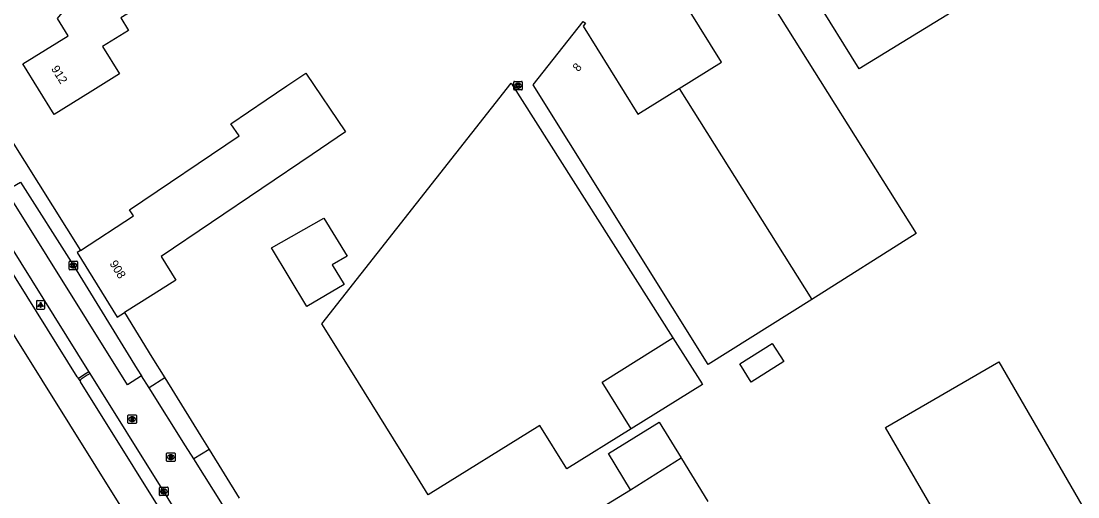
# Model space of a CAD drawing. Extents: x 158461 to 159795, y 387220 to 388672.
# Drawn here: x 158755 to 158879.5, y 387329 to 387385 of the extents above; entities that cross this region are included whole.
import ezdxf

# ---------------------------------------------------------------- set-up
doc = ezdxf.new("R2010")
doc.units = 0
for name, color, linetype in [('IMGEO_Brandkraan', 7, 'Continuous'), ('IMGEO_Haag', 7, 'Continuous'), ('IMGEO_Kolk', 7, 'Continuous'), ('IMGEO_Lichtpunt', 7, 'Continuous'), ('IMGEO_Pand', 7, 'Continuous'), ('IMGEO_Pand_nummerreeks', 7, 'Continuous'), ('IMGEO_Rijbaan_lokaal_open', 7, 'Continuous'), ('IMGEO_Rijbaan_regionaal_gesloten', 7, 'Continuous'), ('IMGEO_Rioolput', 7, 'Continuous'), ('IMGEO_Voetpad_open', 7, 'Continuous')]:
    doc.layers.add(name, color=color, linetype=linetype)

msp = doc.modelspace()

# ---------------------------------------------------------------- linework, layer by layer
at = {"layer": 'IMGEO_Brandkraan'}
for p, q in [((158772.16, 387333.25), (158772.16, 387334.1)), ((158772.24, 387334.18), (158773.09, 387334.18)), ((158772.65, 387333.96), (158772.68, 387333.96)), ((158772.67, 387333.4), (158772.65, 387333.4)), ((158773.16, 387334.1), (158773.16, 387333.25)), ((158773.09, 387333.18), (158772.24, 387333.18))]:
    msp.add_line(p, q, dxfattribs=at)
for points in [[(158772.16, 387333.25), (158772.16, 387334.1)], [(158772.24, 387334.18), (158773.09, 387334.18)], [(158772.51, 387333.88), (158772.51, 387333.48), (158772.72, 387333.48)], [(158772.74, 387333.88), (158772.51, 387333.88)], [(158772.69, 387333.8), (158772.63, 387333.8), (158772.63, 387333.72)], [(158772.63, 387333.72), (158772.69, 387333.72)], [(158772.7, 387333.64), (158772.63, 387333.64), (158772.63, 387333.56)], [(158772.63, 387333.56), (158772.7, 387333.56)], [(158773.16, 387334.1), (158773.16, 387333.25)], [(158773.09, 387333.18), (158772.24, 387333.18)]]:
    msp.add_lwpolyline(points, dxfattribs=at)
for centre, radius, start, end in [((158772.24, 387334.1), 0.0765, 91.552, 178.448), ((158772.24, 387334.1), 0.0765, 91.552, 178.448), ((158772.24, 387333.25), 0.0765, 181.552, 268.448), ((158772.24, 387333.25), 0.0765, 181.552, 268.448), ((158772.69, 387333.76), 0.0379, 267.8285, 90.9355), ((158772.7, 387333.6), 0.0404, 269.8759, 90.5077), ((158772.73, 387333.73), 0.251, 268.6676, 293.5347), ((158772.75, 387333.73), 0.145, 59.4692, 91.5367), ((158772.77, 387333.78), 0.0922, 285.5137, 58.1501), ((158772.77, 387333.59), 0.105, 301.3115, 78.989), ((158773.09, 387334.1), 0.0765, 1.552, 88.448), ((158773.09, 387334.1), 0.0765, 1.552, 88.448), ((158773.09, 387333.25), 0.0765, 271.552, 358.448), ((158773.09, 387333.25), 0.0765, 271.552, 358.448)]:
    msp.add_arc(centre, radius, start, end, dxfattribs=at)
for centre, major_axis, ratio, start_param, end_param in [((158772.65, 387333.68), (-0.387, 0.002), 0.722429, 4.712389, 7.853982), ((158772.67, 387333.68), (-0.39, 0.002), 0.717154, 1.570796, 4.712389)]:
    msp.add_ellipse(centre, major_axis=major_axis, ratio=ratio, start_param=start_param, end_param=end_param, dxfattribs=at)
at = {"layer": 'IMGEO_Haag'}
for points in [[(158761.92, 387343.05), (158762.69, 387343.55), (158763.01, 387343.76)], [(158763.16, 387343.53), (158762.83, 387343.32), (158762.11, 387342.85)]]:
    msp.add_lwpolyline(points, dxfattribs=at)
for centre, radius, start, end in [((158761.82, 387343.19), 0.176, 248.8695, 305.5504), ((158762.26, 387342.65), 0.255, 126.1975, 177.1656)]:
    msp.add_arc(centre, radius, start, end, dxfattribs=at)
at = {"layer": 'IMGEO_Kolk'}
for p, q in [((158813.06, 387376.97), (158813.06, 387377.82)), ((158813.13, 387377.89), (158813.99, 387377.89)), ((158813.99, 387376.89), (158813.13, 387376.89)), ((158813.57, 387377.11), (158813.54, 387377.11)), ((158813.55, 387377.67), (158813.57, 387377.67)), ((158814.06, 387377.82), (158814.06, 387376.97)), ((158760.69, 387355.8), (158760.69, 387356.65)), ((158760.76, 387356.73), (158761.61, 387356.73)), ((158761.61, 387355.73), (158760.76, 387355.73)), ((158761.17, 387356.51), (158761.2, 387356.51)), ((158761.2, 387355.95), (158761.17, 387355.95)), ((158761.69, 387356.65), (158761.69, 387355.8)), ((158771.33, 387329.22), (158771.33, 387330.08)), ((158771.41, 387330.15), (158772.26, 387330.15)), ((158771.82, 387329.93), (158771.85, 387329.93)), ((158772.34, 387330.08), (158772.34, 387329.22)), ((158772.26, 387329.15), (158771.41, 387329.15)), ((158771.84, 387329.37), (158771.82, 387329.37))]:
    msp.add_line(p, q, dxfattribs=at)
for points in [[(158813.06, 387376.97), (158813.06, 387377.82)], [(158813.13, 387377.89), (158813.99, 387377.89)], [(158813.99, 387376.89), (158813.13, 387376.89)], [(158813.38, 387377.59), (158813.5, 387377.59), (158813.5, 387377.44), (158813.63, 387377.59), (158813.8, 387377.59), (158813.65, 387377.44), (158813.8, 387377.19), (158813.65, 387377.19), (158813.57, 387377.36), (158813.5, 387377.29), (158813.5, 387377.19), (158813.38, 387377.19), (158813.38, 387377.59)], [(158814.06, 387377.82), (158814.06, 387376.97)], [(158760.69, 387355.8), (158760.69, 387356.65)], [(158760.76, 387356.73), (158761.61, 387356.73)], [(158761.61, 387355.73), (158760.76, 387355.73)], [(158761.01, 387356.43), (158761.13, 387356.43), (158761.13, 387356.28), (158761.26, 387356.43), (158761.42, 387356.43), (158761.28, 387356.28), (158761.43, 387356.03), (158761.28, 387356.03), (158761.19, 387356.19), (158761.13, 387356.12), (158761.13, 387356.03), (158761.01, 387356.03), (158761.01, 387356.43)], [(158761.69, 387356.65), (158761.69, 387355.8)], [(158771.33, 387329.22), (158771.33, 387330.08)], [(158771.41, 387330.15), (158772.26, 387330.15)], [(158771.65, 387329.85), (158771.78, 387329.85), (158771.78, 387329.7), (158771.91, 387329.85), (158772.07, 387329.85), (158771.93, 387329.7), (158772.08, 387329.45), (158771.93, 387329.45), (158771.84, 387329.61), (158771.78, 387329.55), (158771.78, 387329.45), (158771.65, 387329.45), (158771.65, 387329.85)], [(158772.34, 387330.08), (158772.34, 387329.22)], [(158772.26, 387329.15), (158771.41, 387329.15)]]:
    msp.add_lwpolyline(points, dxfattribs=at)
for centre, start, end in [((158813.13, 387377.82), 91.552, 178.448), ((158813.13, 387377.82), 91.552, 178.448), ((158813.13, 387376.97), 181.552, 268.448), ((158813.13, 387376.97), 181.552, 268.448), ((158813.98, 387377.82), 1.552, 88.448), ((158813.98, 387377.82), 1.552, 88.448), ((158813.98, 387376.97), 271.552, 358.448), ((158813.98, 387376.97), 271.552, 358.448), ((158760.76, 387356.65), 91.552, 178.448), ((158760.76, 387356.65), 91.552, 178.448), ((158760.76, 387355.8), 181.552, 268.448), ((158760.76, 387355.8), 181.552, 268.448), ((158761.61, 387356.65), 1.552, 88.448), ((158761.61, 387356.65), 1.552, 88.448), ((158761.61, 387355.8), 271.552, 358.448), ((158761.61, 387355.8), 271.552, 358.448), ((158771.41, 387330.07), 91.552, 178.448), ((158771.41, 387330.07), 91.552, 178.448), ((158772.26, 387330.07), 1.552, 88.448), ((158772.26, 387330.07), 1.552, 88.448), ((158771.41, 387329.22), 181.552, 268.448), ((158771.41, 387329.22), 181.552, 268.448), ((158772.26, 387329.22), 271.552, 358.448), ((158772.26, 387329.22), 271.552, 358.448)]:
    msp.add_arc(centre, 0.0765, start, end, dxfattribs=at)
for centre, major_axis, ratio, start_param, end_param in [((158813.55, 387377.39), (-0.387, 0.002), 0.722429, 4.712389, 7.853982), ((158813.57, 387377.39), (-0.39, 0.002), 0.717154, 1.570796, 4.712389), ((158761.17, 387356.23), (-0.387, 0.002), 0.722429, 4.712389, 7.853982), ((158761.2, 387356.23), (-0.39, 0.002), 0.717154, 1.570796, 4.712389), ((158771.82, 387329.65), (-0.387, 0.002), 0.722429, 4.712389, 7.853982), ((158771.85, 387329.65), (-0.39, 0.002), 0.717154, 1.570796, 4.712389)]:
    msp.add_ellipse(centre, major_axis=major_axis, ratio=ratio, start_param=start_param, end_param=end_param, dxfattribs=at)
at = {"layer": 'IMGEO_Lichtpunt'}
for p, q in [((158756.83, 387352), (158756.83, 387351.19)), ((158756.83, 387352), (158756.83, 387351.19)), ((158757.73, 387352.09), (158756.93, 387352.09)), ((158757.73, 387352.09), (158756.93, 387352.09)), ((158757.83, 387351.19), (158757.83, 387352)), ((158757.83, 387351.19), (158757.83, 387352)), ((158756.93, 387351.09), (158757.73, 387351.09)), ((158756.93, 387351.09), (158757.73, 387351.09))]:
    msp.add_line(p, q, dxfattribs=at)
for points in [[(158757.21, 387351.66), (158757.24, 387351.63), (158757.06, 387351.37), (158757.02, 387351.4), (158757.21, 387351.66)], [(158757.31, 387351.61), (158757.35, 387351.61), (158757.35, 387351.29), (158757.31, 387351.29), (158757.31, 387351.61)], [(158757.42, 387351.63), (158757.46, 387351.66), (158757.64, 387351.4), (158757.6, 387351.37), (158757.42, 387351.63)]]:
    msp.add_lwpolyline(points, dxfattribs=at)
msp.add_circle((158757.33, 387351.79), 0.0994, dxfattribs=at)
for centre, start, end in [((158756.93, 387352), 90, 180), ((158756.93, 387352), 90, 180), ((158757.73, 387352), 0, 90), ((158757.73, 387352), 0, 90), ((158756.93, 387351.19), 180, 270), ((158756.93, 387351.19), 180, 270), ((158757.73, 387351.19), 270, 0), ((158757.73, 387351.19), 270, 360)]:
    msp.add_arc(centre, 0.0946, start, end, dxfattribs=at)
at = {"layer": 'IMGEO_Pand'}
for points in [[(158853.76, 387379.38), (158848.51, 387387.8), (158861.3, 387395.65), (158861.6, 387395.16), (158864.38, 387390.64), (158866.49, 387387.19), (158853.76, 387379.38)], [(158766.63, 387378.77), (158763.16, 387376.62), (158758.91, 387373.99), (158755.22, 387379.95), (158760.57, 387383.26), (158759.32, 387385.28), (158763.48, 387390.37), (158767.04, 387392.57), (158770.18, 387387.5), (158766.77, 387385.39), (158767.7, 387383.9), (158764.63, 387382), (158766.63, 387378.77)], [(158832.55, 387377.07), (158837.53, 387380.17), (158833.66, 387386.4), (158840.69, 387390.82), (158840.46, 387391.19), (158840.73, 387391.36), (158842.81, 387388.05), (158860.46, 387359.98), (158848.15, 387352.24)], [(158848.15, 387352.24), (158835.96, 387344.58), (158815.33, 387377.48), (158821.23, 387384.94), (158821.49, 387384.76), (158821.22, 387384.4), (158827.66, 387374.03), (158832.55, 387377.07)], [(158762.02, 387358), (158768.27, 387362.07), (158767.8, 387362.77), (158780.71, 387371.49), (158779.74, 387372.92), (158783.88, 387375.72), (158786.33, 387377.36), (158788.57, 387378.88), (158793.25, 387371.95), (158789.3, 387369.28), (158771.52, 387357.27), (158773.27, 387354.49), (158770.6, 387352.82), (158767.23, 387350.71)], [(158826.9, 387337), (158819.32, 387332.29), (158816.14, 387337.41), (158802.98, 387329.24), (158801.39, 387331.8), (158793.87, 387343.92), (158790.47, 387349.36), (158812.74, 387377.68), (158831.8, 387347.72)], [(158832.55, 387377.07), (158848.15, 387352.24)], [(158788.68, 387351.4), (158784.51, 387358.32), (158790.69, 387361.8), (158793.43, 387357.31), (158791.66, 387356.29), (158793.07, 387353.99), (158788.68, 387351.4)], [(158762.02, 387358), (158761.64, 387357.75), (158766.36, 387350.16), (158767.23, 387350.71)], [(158826.9, 387337), (158823.46, 387342.49), (158831.8, 387347.72)], [(158831.8, 387347.72), (158835.24, 387342.31), (158835.3, 387342.21), (158826.9, 387337)], [(158841.02, 387342.52), (158839.68, 387344.65), (158843.51, 387347.05), (158844.85, 387344.92), (158841.02, 387342.52)], [(158885.44, 387318.61), (158872.12, 387310.88), (158856.86, 387337.18), (158870.18, 387344.91), (158885.44, 387318.61)], [(158826.81, 387329.84), (158824.2, 387334.11), (158830.2, 387337.78), (158832.76, 387333.6)], [(158826.81, 387329.84), (158832.76, 387333.6)], [(158832.76, 387333.6), (158832.81, 387333.51), (158835.9, 387328.46)], [(158823.08, 387320.48), (158819.93, 387325.62), (158826.81, 387329.84)]]:
    msp.add_lwpolyline(points, dxfattribs=at)
at = {"layer": 'IMGEO_Rijbaan_lokaal_open'}
for points in [[(158769.22, 387343.24), (158767.55, 387342.19), (158753.27, 387365.05), (158754.95, 387366.05)], [(158763.01, 387343.76), (158749.64, 387365.16)], [(158763.16, 387343.53), (158763.01, 387343.76)], [(158776, 387322.91), (158771.83, 387329.65), (158763.16, 387343.53)], [(158770.1, 387341.85), (158769.22, 387343.24)], [(158775.37, 387333.47), (158774.4, 387335), (158770.1, 387341.85)], [(158778.94, 387327.79), (158775.37, 387333.47)]]:
    msp.add_lwpolyline(points, dxfattribs=at)
at = {"layer": 'IMGEO_Rijbaan_regionaal_gesloten'}
for points in [[(158824.18, 387235.99), (158792.36, 387286.93), (158694.26, 387443.97), (158684.57, 387459.46), (158661.98, 387495.7), (158658.09, 387501.91), (158642.29, 387527.16), (158630.02, 387546.72), (158625.56, 387554.19)], [(158761.76, 387343.03), (158761.65, 387343.14), (158748.54, 387364.12)], [(158762, 387342.66), (158761.76, 387343.03)], [(158774.63, 387322.38), (158762.03, 387342.54)]]:
    msp.add_lwpolyline(points, dxfattribs=at)
msp.add_arc((158762.25, 387342.65), 0.251, 176.7515, 204.9487, dxfattribs=at)
at = {"layer": 'IMGEO_Rioolput'}
for p, q in [((158767.61, 387337.71), (158767.61, 387338.57)), ((158767.68, 387338.64), (158768.54, 387338.64)), ((158768.1, 387338.42), (158768.12, 387338.42)), ((158768.61, 387338.57), (158768.61, 387337.71)), ((158768.54, 387337.64), (158767.68, 387337.64)), ((158768.12, 387337.86), (158768.09, 387337.86))]:
    msp.add_line(p, q, dxfattribs=at)
for points in [[(158767.61, 387337.71), (158767.61, 387338.57)], [(158767.68, 387338.64), (158768.54, 387338.64)], [(158768.2, 387338.34), (158767.94, 387338.34), (158767.94, 387337.94)], [(158768.12, 387338.26), (158768.07, 387338.26), (158768.07, 387338.18)], [(158768.61, 387338.57), (158768.61, 387337.71)], [(158768.54, 387337.64), (158767.68, 387337.64)], [(158767.94, 387337.94), (158768.07, 387337.94), (158768.07, 387338.1), (158768.08, 387338.1)], [(158768.07, 387338.18), (158768.12, 387338.18)], [(158768.13, 387338.07), (158768.2, 387337.94), (158768.34, 387337.94), (158768.27, 387338.07)]]:
    msp.add_lwpolyline(points, dxfattribs=at)
for centre, radius, start, end in [((158767.68, 387338.56), 0.0765, 91.552, 178.448), ((158767.68, 387338.56), 0.0765, 91.552, 178.448), ((158768.13, 387338.16), 0.0964, 77.0061, 93.1865), ((158768.14, 387338.22), 0.0378, 276.6634, 79.6772), ((158768.2, 387338.23), 0.109, 350.3612, 89.416), ((158768.19, 387338.23), 0.112, 277.5842, 350.9817), ((158768.53, 387338.56), 0.0765, 1.552, 88.448), ((158768.53, 387338.56), 0.0765, 1.552, 88.448), ((158767.68, 387337.71), 0.0765, 181.552, 268.448), ((158767.68, 387337.71), 0.0765, 181.552, 268.448), ((158768.08, 387338.05), 0.0533, 26.0293, 88.6989), ((158768.11, 387338.37), 0.19, 274.7715, 282.9687), ((158768.18, 387338.01), 0.108, 29.5134, 73.7905), ((158768.53, 387337.71), 0.0765, 271.552, 358.448), ((158768.53, 387337.71), 0.0765, 271.552, 358.448)]:
    msp.add_arc(centre, radius, start, end, dxfattribs=at)
for centre, major_axis, ratio, start_param, end_param in [((158768.1, 387338.14), (-0.387, 0.002), 0.722429, 4.712389, 7.853982), ((158768.12, 387338.14), (-0.39, 0.002), 0.717154, 1.570796, 4.712389)]:
    msp.add_ellipse(centre, major_axis=major_axis, ratio=ratio, start_param=start_param, end_param=end_param, dxfattribs=at)
at = {"layer": 'IMGEO_Voetpad_open'}
for points in [[(158750.44, 387376.4), (158762.02, 387358)], [(158754.95, 387366.05), (158761.19, 387356.23), (158768.71, 387344.05), (158769.22, 387343.24)], [(158767.23, 387350.71), (158770.44, 387345.44), (158771.95, 387343.01)], [(158771.95, 387343.01), (158770.1, 387341.85)], [(158771.95, 387343.01), (158776.19, 387336.16), (158777.18, 387334.57)], [(158777.18, 387334.57), (158775.37, 387333.47)], [(158777.18, 387334.57), (158780.72, 387328.86)]]:
    msp.add_lwpolyline(points, dxfattribs=at)

# ---------------------------------------------------------------- texts
at = {"layer": 'IMGEO_Pand_nummerreeks'}
for s, rotation, p in [('912', 301.787, (158758.53, 387379.39)), ('8', 51.6581, (158820.68, 387378.97)), ('908', 301.9028, (158765.41, 387356.46))]:
    msp.add_text(s, height=1, rotation=rotation, dxfattribs=at).set_placement(p)

doc.saveas('drawing.dxf')
